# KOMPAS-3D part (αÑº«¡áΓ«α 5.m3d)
File: created 29.01.2016 13:47:21, last saved 27.07.2016 14:59:16.
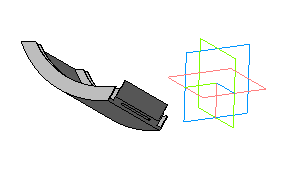
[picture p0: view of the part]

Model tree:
1. Эскиз:1
2. Операция выдавливания:1
     Толщина стенки 1 = 2; Толщина стенки 2 = 8; Расстояние 1 = 1
3. Эскиз:2
4. Операция выдавливания:2
     Толщина стенки 1 = 2; Толщина стенки 2 = 8; Расстояние 1 = 5
5. Эскиз:3
6. Операция выдавливания:3
     Толщина стенки 1 = 2; Толщина стенки 2 = 8; Расстояние 1 = 1
7. Эскиз:4
8. Операция выдавливания:4
     Толщина стенки 1 = 2; Толщина стенки 2 = 2.5; Расстояние 1 = 50
9. Эскиз:5
10. Вырезать элемент выдавливания:1
     Толщина стенки 2 = 1.2; Расстояние 1 = 40
11. Эскиз:6
12. Операция выдавливания:5
     Толщина стенки 1 = 2; Толщина стенки 2 = 2.5; Расстояние 1 = 10
13. Эскиз:7
14. Операция выдавливания:6
     Толщина стенки 1 = 2; Толщина стенки 2 = 8; Расстояние 1 = 1
15. Эскиз:8
16. Операция выдавливания:7
     Толщина стенки 1 = 2; Толщина стенки 2 = 8; Расстояние 1 = 5
17. Эскиз:9
18. Операция выдавливания:8
     Толщина стенки 1 = 2; Толщина стенки 2 = 8; Расстояние 1 = 1
19. Эскиз:10
20. Вырезать элемент выдавливания:2
     Толщина стенки 2 = 1.2; Расстояние 1 = 23
21. Эскиз:11
22. Вырезать элемент выдавливания:3
     Толщина стенки 2 = 1.2; Расстояние 1 = 1
23. Эскиз:12
24. Вырезать элемент выдавливания:4
     Расстояние 1 = 100
25. Эскиз:13
26. Операция выдавливания:9
     Расстояние 1 = 10; Расстояние 2 = 0.4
